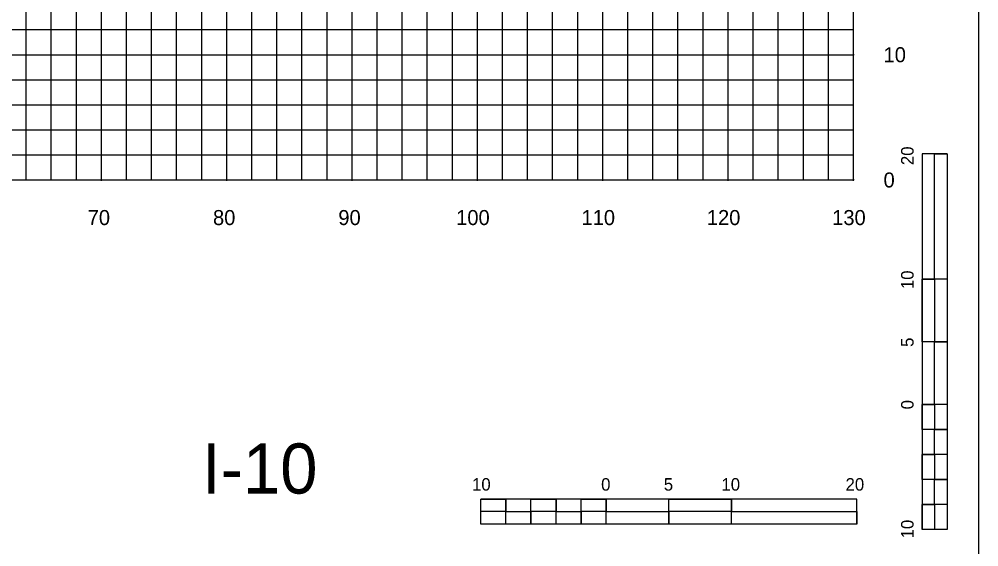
# Model space of a CAD drawing. Extents: x 2193008 to 2198143, y 1236112 to 1237864.
# Drawn here: x 2194956.3 to 2195032.9, y 1237228.8 to 1237270.9 of the extents above; entities that cross this region are included whole.
import ezdxf

# ---------------------------------------------------------------- set-up
doc = ezdxf.new("R2010")
doc.units = 0
for name, color, linetype in [('3', 7, 'Continuous'), ('31', 7, 'Continuous'), ('60', 7, 'Continuous'), ('Level 1', 7, 'Continuous'), ('Level 33', 7, 'Continuous'), ('LIMT-CSLINE', 7, 'Continuous'), ('M-ROADS', 7, 'Continuous')]:
    doc.layers.add(name, color=color, linetype=linetype)

msp = doc.modelspace()

# ---------------------------------------------------------------- linework, layer by layer
at = {"layer": '3'}
msp.add_line((2195032.86, 1237228.046), (2195032.86, 1237323.046), dxfattribs=at)
at = {"layer": '60'}
for p, q in [((2195022.86, 1237258.106), (2195022.86, 1237318.106)), ((2195022.92, 1237268.106), (2195022.86, 1237268.106)), ((2194892.86, 1237258.106), (2195022.86, 1237258.106)), ((2194962.86, 1237258.046), (2194962.86, 1237258.106)), ((2194972.86, 1237258.046), (2194972.86, 1237258.106)), ((2194982.86, 1237258.046), (2194982.86, 1237258.106)), ((2194992.86, 1237258.046), (2194992.86, 1237258.106)), ((2195002.86, 1237258.046), (2195002.86, 1237258.106)), ((2195012.86, 1237258.046), (2195012.86, 1237258.106)), ((2195022.86, 1237258.046), (2195022.86, 1237258.106)), ((2195022.92, 1237258.106), (2195022.86, 1237258.106))]:
    msp.add_line(p, q, dxfattribs=at)
at = {"layer": 'Level 1'}
for p, q in [((2195028.332, 1237260.195), (2195028.332, 1237230.195)), ((2195030.332, 1237260.195), (2195028.332, 1237260.195)), ((2195028.332, 1237260.195), (2195028.332, 1237230.195)), ((2195030.332, 1237260.195), (2195028.332, 1237260.195)), ((2195030.332, 1237260.195), (2195030.332, 1237250.195)), ((2195030.332, 1237260.195), (2195030.332, 1237230.195)), ((2195030.332, 1237260.195), (2195030.332, 1237250.195)), ((2195030.332, 1237260.195), (2195030.332, 1237230.195)), ((2195029.332, 1237250.195), (2195028.332, 1237250.195)), ((2195030.332, 1237250.195), (2195028.332, 1237250.195)), ((2195029.332, 1237250.195), (2195028.332, 1237250.195)), ((2195030.332, 1237250.195), (2195028.332, 1237250.195)), ((2195029.332, 1237250.195), (2195029.332, 1237245.195)), ((2195029.332, 1237250.195), (2195029.332, 1237245.195)), ((2195030.332, 1237245.195), (2195028.332, 1237245.195)), ((2195030.332, 1237245.195), (2195028.332, 1237245.195)), ((2195030.332, 1237245.195), (2195029.332, 1237245.195)), ((2195030.332, 1237245.195), (2195029.332, 1237245.195)), ((2195030.332, 1237245.195), (2195030.332, 1237240.195)), ((2195030.332, 1237245.195), (2195030.332, 1237240.195)), ((2195029.332, 1237240.195), (2195028.332, 1237240.195)), ((2195030.332, 1237240.195), (2195028.332, 1237240.195)), ((2195029.332, 1237240.195), (2195028.332, 1237240.195)), ((2195030.332, 1237240.195), (2195028.332, 1237240.195)), ((2195029.332, 1237240.195), (2195029.332, 1237238.195)), ((2195029.332, 1237240.195), (2195029.332, 1237238.195)), ((2195030.332, 1237238.195), (2195029.332, 1237238.195)), ((2195030.332, 1237238.195), (2195029.332, 1237238.195)), ((2195030.332, 1237238.195), (2195030.332, 1237236.195)), ((2195030.332, 1237238.195), (2195030.332, 1237236.195)), ((2195029.332, 1237236.195), (2195028.332, 1237236.195)), ((2195029.332, 1237236.195), (2195028.332, 1237236.195)), ((2195029.332, 1237236.195), (2195029.332, 1237234.195)), ((2195029.332, 1237236.195), (2195029.332, 1237234.195)), ((2195030.332, 1237234.195), (2195029.332, 1237234.195)), ((2195030.332, 1237234.195), (2195029.332, 1237234.195)), ((2195030.332, 1237234.195), (2195030.332, 1237232.195)), ((2195030.332, 1237234.195), (2195030.332, 1237232.195)), ((2195023.128, 1237232.63), (2194993.128, 1237232.63)), ((2194993.128, 1237230.63), (2194993.128, 1237232.63)), ((2195023.128, 1237232.63), (2194993.128, 1237232.63)), ((2194993.128, 1237230.63), (2194993.128, 1237232.63)), ((2194995.128, 1237231.63), (2194995.128, 1237232.63)), ((2194995.128, 1237231.63), (2194995.128, 1237232.63)), ((2194999.128, 1237231.63), (2194999.128, 1237232.63)), ((2194999.128, 1237231.63), (2194999.128, 1237232.63)), ((2195003.128, 1237231.63), (2195003.128, 1237232.63)), ((2195003.128, 1237230.63), (2195003.128, 1237232.63)), ((2195003.128, 1237231.63), (2195003.128, 1237232.63)), ((2195003.128, 1237230.63), (2195003.128, 1237232.63)), ((2195008.128, 1237230.63), (2195008.128, 1237232.63)), ((2195008.128, 1237230.63), (2195008.128, 1237232.63)), ((2195013.128, 1237231.63), (2195013.128, 1237232.63)), ((2195013.128, 1237230.63), (2195013.128, 1237232.63)), ((2195013.128, 1237231.63), (2195013.128, 1237232.63)), ((2195013.128, 1237230.63), (2195013.128, 1237232.63)), ((2195023.128, 1237230.63), (2195023.128, 1237232.63)), ((2195023.128, 1237230.63), (2195023.128, 1237232.63)), ((2194995.128, 1237231.63), (2194993.128, 1237231.63)), ((2194995.128, 1237231.63), (2194993.128, 1237231.63)), ((2194997.128, 1237230.63), (2194997.128, 1237231.63)), ((2194999.128, 1237231.63), (2194997.128, 1237231.63)), ((2194997.128, 1237230.63), (2194997.128, 1237231.63)), ((2194999.128, 1237231.63), (2194997.128, 1237231.63)), ((2195001.128, 1237230.63), (2195001.128, 1237231.63)), ((2195003.128, 1237231.63), (2195001.128, 1237231.63)), ((2195001.128, 1237230.63), (2195001.128, 1237231.63)), ((2195003.128, 1237231.63), (2195001.128, 1237231.63)), ((2195008.128, 1237230.63), (2195008.128, 1237231.63)), ((2195013.128, 1237231.63), (2195008.128, 1237231.63)), ((2195008.128, 1237230.63), (2195008.128, 1237231.63)), ((2195013.128, 1237231.63), (2195008.128, 1237231.63)), ((2195029.332, 1237232.195), (2195028.332, 1237232.195)), ((2195029.332, 1237232.195), (2195028.332, 1237232.195)), ((2195029.332, 1237232.195), (2195029.332, 1237230.195)), ((2195029.332, 1237232.195), (2195029.332, 1237230.195)), ((2195023.128, 1237230.63), (2194993.128, 1237230.63)), ((2195023.128, 1237230.63), (2194993.128, 1237230.63)), ((2194997.128, 1237230.63), (2194995.128, 1237230.63)), ((2194997.128, 1237230.63), (2194995.128, 1237230.63)), ((2195001.128, 1237230.63), (2194999.128, 1237230.63)), ((2195001.128, 1237230.63), (2194999.128, 1237230.63)), ((2195008.128, 1237230.63), (2195003.128, 1237230.63)), ((2195008.128, 1237230.63), (2195003.128, 1237230.63)), ((2195023.128, 1237230.63), (2195013.128, 1237230.63)), ((2195023.128, 1237230.63), (2195013.128, 1237230.63)), ((2195030.332, 1237230.195), (2195028.332, 1237230.195)), ((2195030.332, 1237230.195), (2195028.332, 1237230.195))]:
    msp.add_line(p, q, dxfattribs=at)
for points in [[(2195029.332, 1237250.195), (2195029.332, 1237260.195), (2195030.332, 1237260.195), (2195030.332, 1237250.195)], [(2195029.332, 1237250.195), (2195029.332, 1237260.195), (2195030.332, 1237260.195), (2195030.332, 1237250.195)], [(2195028.332, 1237245.195), (2195028.332, 1237250.195), (2195029.332, 1237250.195), (2195029.332, 1237245.195)], [(2195028.332, 1237245.195), (2195028.332, 1237250.195), (2195029.332, 1237250.195), (2195029.332, 1237245.195)], [(2195029.332, 1237240.195), (2195029.332, 1237245.195), (2195030.332, 1237245.195), (2195030.332, 1237240.195)], [(2195029.332, 1237240.195), (2195029.332, 1237245.195), (2195030.332, 1237245.195), (2195030.332, 1237240.195)], [(2195028.332, 1237238.195), (2195028.332, 1237240.195), (2195029.332, 1237240.195), (2195029.332, 1237238.195)], [(2195028.332, 1237238.195), (2195028.332, 1237240.195), (2195029.332, 1237240.195), (2195029.332, 1237238.195)], [(2195029.332, 1237236.195), (2195029.332, 1237238.195), (2195030.332, 1237238.195), (2195030.332, 1237236.195)], [(2195029.332, 1237236.195), (2195029.332, 1237238.195), (2195030.332, 1237238.195), (2195030.332, 1237236.195)], [(2195028.332, 1237234.195), (2195028.332, 1237236.195), (2195029.332, 1237236.195), (2195029.332, 1237234.195)], [(2195028.332, 1237234.195), (2195028.332, 1237236.195), (2195029.332, 1237236.195), (2195029.332, 1237234.195)], [(2195029.332, 1237232.195), (2195029.332, 1237234.195), (2195030.332, 1237234.195), (2195030.332, 1237232.195)], [(2195029.332, 1237232.195), (2195029.332, 1237234.195), (2195030.332, 1237234.195), (2195030.332, 1237232.195)], [(2194993.128, 1237232.63), (2194995.128, 1237232.63), (2194995.128, 1237231.63), (2194993.128, 1237231.63)], [(2194993.128, 1237232.63), (2194995.128, 1237232.63), (2194995.128, 1237231.63), (2194993.128, 1237231.63)], [(2194997.128, 1237232.63), (2194999.128, 1237232.63), (2194999.128, 1237231.63), (2194997.128, 1237231.63)], [(2194997.128, 1237232.63), (2194999.128, 1237232.63), (2194999.128, 1237231.63), (2194997.128, 1237231.63)], [(2195001.128, 1237232.63), (2195003.128, 1237232.63), (2195003.128, 1237231.63), (2195001.128, 1237231.63)], [(2195001.128, 1237232.63), (2195003.128, 1237232.63), (2195003.128, 1237231.63), (2195001.128, 1237231.63)], [(2195008.128, 1237232.63), (2195013.128, 1237232.63), (2195013.128, 1237231.63), (2195008.128, 1237231.63)], [(2195008.128, 1237232.63), (2195013.128, 1237232.63), (2195013.128, 1237231.63), (2195008.128, 1237231.63)], [(2194995.128, 1237231.63), (2194997.128, 1237231.63), (2194997.128, 1237230.63), (2194995.128, 1237230.63)], [(2194995.128, 1237231.63), (2194997.128, 1237231.63), (2194997.128, 1237230.63), (2194995.128, 1237230.63)], [(2194999.128, 1237231.63), (2195001.128, 1237231.63), (2195001.128, 1237230.63), (2194999.128, 1237230.63)], [(2194999.128, 1237231.63), (2195001.128, 1237231.63), (2195001.128, 1237230.63), (2194999.128, 1237230.63)], [(2195003.128, 1237231.63), (2195008.128, 1237231.63), (2195008.128, 1237230.63), (2195003.128, 1237230.63)], [(2195003.128, 1237231.63), (2195008.128, 1237231.63), (2195008.128, 1237230.63), (2195003.128, 1237230.63)], [(2195013.128, 1237231.63), (2195023.128, 1237231.63), (2195023.128, 1237230.63), (2195013.128, 1237230.63)], [(2195013.128, 1237231.63), (2195023.128, 1237231.63), (2195023.128, 1237230.63), (2195013.128, 1237230.63)], [(2195028.332, 1237230.195), (2195028.332, 1237232.195), (2195029.332, 1237232.195), (2195029.332, 1237230.195)], [(2195028.332, 1237230.195), (2195028.332, 1237232.195), (2195029.332, 1237232.195), (2195029.332, 1237230.195)]]:
    msp.add_lwpolyline(points, close=True, dxfattribs=at)
at = {"layer": 'M-ROADS'}
for p, q in [((2194956.86, 1237258.106), (2194956.86, 1237318.106)), ((2194958.86, 1237258.106), (2194958.86, 1237318.106)), ((2194960.86, 1237258.106), (2194960.86, 1237318.106)), ((2194962.86, 1237258.106), (2194962.86, 1237318.106)), ((2194964.86, 1237258.106), (2194964.86, 1237318.106)), ((2194966.86, 1237258.106), (2194966.86, 1237318.106)), ((2194968.86, 1237258.106), (2194968.86, 1237318.106)), ((2194970.86, 1237258.106), (2194970.86, 1237318.106)), ((2194972.86, 1237258.106), (2194972.86, 1237318.106)), ((2194974.86, 1237258.106), (2194974.86, 1237318.106)), ((2194976.86, 1237258.106), (2194976.86, 1237318.106)), ((2194978.86, 1237258.106), (2194978.86, 1237318.106)), ((2194980.86, 1237258.106), (2194980.86, 1237318.106)), ((2194982.86, 1237258.106), (2194982.86, 1237318.106)), ((2194984.86, 1237258.106), (2194984.86, 1237318.106)), ((2194986.86, 1237258.106), (2194986.86, 1237318.106)), ((2194988.86, 1237258.106), (2194988.86, 1237318.106)), ((2194990.86, 1237258.106), (2194990.86, 1237318.106)), ((2194992.86, 1237258.106), (2194992.86, 1237318.106)), ((2194994.86, 1237258.106), (2194994.86, 1237318.106)), ((2194996.86, 1237258.106), (2194996.86, 1237318.106)), ((2194998.86, 1237258.106), (2194998.86, 1237318.106)), ((2195000.86, 1237258.106), (2195000.86, 1237318.106)), ((2195002.86, 1237258.106), (2195002.86, 1237318.106)), ((2195004.86, 1237258.106), (2195004.86, 1237318.106)), ((2195006.86, 1237258.106), (2195006.86, 1237318.106)), ((2195008.86, 1237258.106), (2195008.86, 1237318.106)), ((2195010.86, 1237258.106), (2195010.86, 1237318.106)), ((2195012.86, 1237258.106), (2195012.86, 1237318.106)), ((2195014.86, 1237258.106), (2195014.86, 1237318.106)), ((2195016.86, 1237258.106), (2195016.86, 1237318.106)), ((2195018.86, 1237258.106), (2195018.86, 1237318.106)), ((2195020.86, 1237258.106), (2195020.86, 1237318.106)), ((2195022.86, 1237258.106), (2195022.86, 1237318.106)), ((2194892.86, 1237270.106), (2195022.86, 1237270.106)), ((2194892.86, 1237268.106), (2195022.86, 1237268.106)), ((2194892.86, 1237266.106), (2195022.86, 1237266.106)), ((2194892.86, 1237264.106), (2195022.86, 1237264.106)), ((2194892.86, 1237262.106), (2195022.86, 1237262.106)), ((2194892.86, 1237260.106), (2195022.86, 1237260.106)), ((2194892.86, 1237258.106), (2195022.86, 1237258.106))]:
    msp.add_line(p, q, dxfattribs=at)

# ---------------------------------------------------------------- texts
at = {"layer": '31'}
for s, p in [('10', (2195025.26, 1237267.506)), ('0', (2195025.26, 1237257.506))]:
    msp.add_text(s, height=1.2, dxfattribs=at).set_placement(p)
at = {"layer": 'Level 1'}
for s, height, rotation, p in [('20', 0.9991, 90.0572, (2195027.658, 1237259.295)), ('20', 0.9991, 90.0572, (2195027.658, 1237259.295)), ('10', 0.9991, 90.0572, (2195027.658, 1237249.395)), ('10', 0.9991, 90.0572, (2195027.658, 1237249.395)), ('5', 1, 90.0572, (2195027.658, 1237244.78)), ('5', 1, 90.0572, (2195027.658, 1237244.78)), ('0', 1, 90.0572, (2195027.658, 1237239.795)), ('0', 1, 90.0572, (2195027.658, 1237239.795)), ('10', 0.9991, 0.0572, (2194992.428, 1237233.305)), ('10', 0.9991, 0.0572, (2194992.428, 1237233.305)), ('0', 1, 0.0572, (2195002.728, 1237233.304)), ('0', 1, 0.0572, (2195002.728, 1237233.304)), ('5', 0.999, 0.0572, (2195007.729, 1237233.304)), ('5', 0.999, 0.0572, (2195007.729, 1237233.304)), ('10', 0.9991, 0.0572, (2195012.328, 1237233.305)), ('10', 0.9991, 0.0572, (2195012.328, 1237233.305)), ('20', 0.9991, 0.0572, (2195022.229, 1237233.305)), ('20', 0.9991, 0.0572, (2195022.229, 1237233.305)), ('10', 0.9991, 90.0572, (2195027.658, 1237229.495)), ('10', 0.9991, 90.0572, (2195027.658, 1237229.495))]:
    msp.add_text(s, height=height, rotation=rotation, dxfattribs=at).set_placement(p)
at = {"layer": 'Level 33'}
msp.add_text('I-10', height=3.9977, rotation=360, dxfattribs=at).set_placement((2194970.885, 1237233.073))
at = {"layer": 'LIMT-CSLINE'}
for s, p in [('70', (2194961.76, 1237254.506)), ('80', (2194971.76, 1237254.506)), ('90', (2194981.76, 1237254.506)), ('100', (2194991.16, 1237254.506)), ('110', (2195001.16, 1237254.506)), ('120', (2195011.16, 1237254.506)), ('130', (2195021.16, 1237254.506))]:
    msp.add_text(s, height=1.2, dxfattribs=at).set_placement(p)

doc.saveas('drawing.dxf')
